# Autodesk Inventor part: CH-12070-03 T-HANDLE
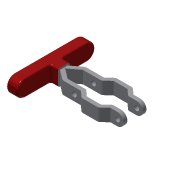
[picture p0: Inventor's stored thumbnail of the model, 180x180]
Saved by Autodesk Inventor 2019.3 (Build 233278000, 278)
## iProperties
Created: 2015-08
Part Number: CH-12070-03 T-HANDLE
Material: Ogólny
Document SubType Name: Modeling
Designer: CADENGINEERING4
Density: 1 g/cm^3
Appearance: Domyślna
Author: CADENGINEERING4
Revision Number: ÈÎºÎ
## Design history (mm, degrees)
feature "NONE"
node "Bryła1"
